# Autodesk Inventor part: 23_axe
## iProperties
Created: 2002-11
Part Number: 23_axe
Material: Par défaut
Document SubType Name: Modélisation
Designer: FIEVET
Control State: 0
Master: False
Checked Out: False
Shininess: 31.0
Length Units: 11269
Angle Units: 11279
Time Units: 11290
Mass Units: 11283
Length Display Precision: 3
Angle Display Precision: 2
Compacted: True
Density: 0.0
Volumn: 0.0
Area: 0.0
PropertySet Name: Model Information
Author: FIEVET
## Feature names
1. Révolution1 [Revolution]
